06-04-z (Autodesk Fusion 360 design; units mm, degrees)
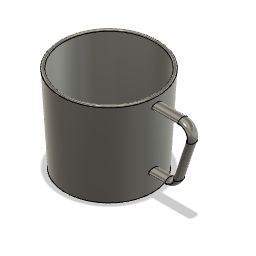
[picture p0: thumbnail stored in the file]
sketch "スケッチ1" plane through (0, 0, 0) normal (0, 0, 1) x axis (1, 0, 0)
  line L1 (0, 45) -> (0, 0)
  line L2 (-25, 45) -> (0, 45)
  line L3 (-22.5, 0) -> (-25, 45)
  line L4 (0, 0) -> (-22.5, 0)
  point P1 (0, 0)
  point P2 (0, 0)
  point P3 (0, 45)
  point P5 (-22.5, 0)
  coincident P1 P2
  vertical L1
  perpendicular L1 L2
  perpendicular L1 L4
  dimension "d1" = 50
  dimension "d2" distance P2 P3 = 45
  dimension "d3" distance L1 P5 = 45
revolve "回転" sketch "スケッチ1" AlongAngle 360
shell "シェル" innerThickness 1.5
offset_faces "面をオフセット" distance 1.5
sketch "スケッチ2" plane through (0, 0, 0) normal (0, 0, 1) x axis (1, 0, 0)
  line L1 (38.0629, 40) -> (24.7222, 40)
  line L2 (36.1396, 13.4189) -> (42.8063, 33.4189)
  line L3 (23.0556, 10) -> (31.3962, 10)
  line L4 (-22.5, 0) -> (-25, 45)
  line L5 (25, 45) -> (22.5, 0)
  line L6 (-22.5, 0) -> (22.5, 0)
  arc A1 centre (38.0629, 35) radius 5 clockwise from (38.0629, 40) to (42.8063, 33.4189)
  arc A2 centre (31.3962, 15) radius 5 clockwise from (36.1396, 13.4189) to (31.3962, 10)
  point P2 (24.7222, 40)
  point P5 (23.0556, 10)
  point P3 (45, 40)
  point P4 (35, 10)
  point P1 (0, 0)
  horizontal L1
  parallel L1 L3
  coincident P2 L5
  coincident P5 L5
  coincident P3 L1
  coincident P3 L2
  tangent L1 A1
  tangent L2 A1
  coincident P4 L2
  coincident P4 L3
  tangent L2 A2
  tangent L3 A2
  equal A1 A2
  dimension "d7" distance P1 P4 = 35
  dimension "d8" distance P1 P3 = 45
  dimension "d9" distance L3 L6 = 10
  dimension "d11" distance P3 P4 = 30
  dimension "d12" radius A1 = 5
work_plane "作業平面" PathDistance 0.1
sketch "スケッチ3" plane through (30.5693, 40, 0) normal (1, 0, 0) x axis (0, 1, 0)
  curve K1 (0, -2.5) -> (0, 2.5)
  curve K2 (1.5, 0) -> (-1.5, 0)
  closed curve K3 centre (0, 0)
  point P1 (0, 0)
  point P2 (0, 0)
  point P3 (0, 2.5)
  point P4 (0, -2.5)
  point P5 (-1.5, 0)
  point P6 (1.5, 0)
  coincident P1 P2
  vertical K1
  coincident K3 P3
  coincident K3 P4
  coincident K3 P5
  coincident K3 P6
  dimension "d14" = 3
  dimension "d15" distance K3 = 5
sweep "スイープ" sketch "スケッチ3" TwistAngle 0 TaperAngle 0
extrude "押し出し1" add of existing geometry to an object
extrude "押し出し2" add of existing geometry to an object
fillet "フィレット1" radius 2
fillet "フィレット2" radius 0.75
